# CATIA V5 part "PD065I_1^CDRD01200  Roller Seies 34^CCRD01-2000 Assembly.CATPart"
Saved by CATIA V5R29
Part number: PD065I_1^CDRD01200  Roller Seies 34^CCRD01-2000 Assembly
Definition: PD065I_1
Nomenclature: PD065I_Drum
Source: Unknown
Bounding box of the stored display mesh (mm): x -29.98 to 29.98, y 184 to 607.977, z -30 to 30
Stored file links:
  C:\가치같이\SmartFactory_BoxErectorConveyor\PD065I_1^CDRD01200  Roller Seies 34^CCRD01-2000 Assembly.CATPart
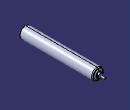
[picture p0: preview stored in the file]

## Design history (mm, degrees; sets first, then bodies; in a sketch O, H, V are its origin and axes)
Body1 "Revolve4" (main body)
  Solid1: solid without history
Body2 "Chamfer2"
  Solid2: solid without history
